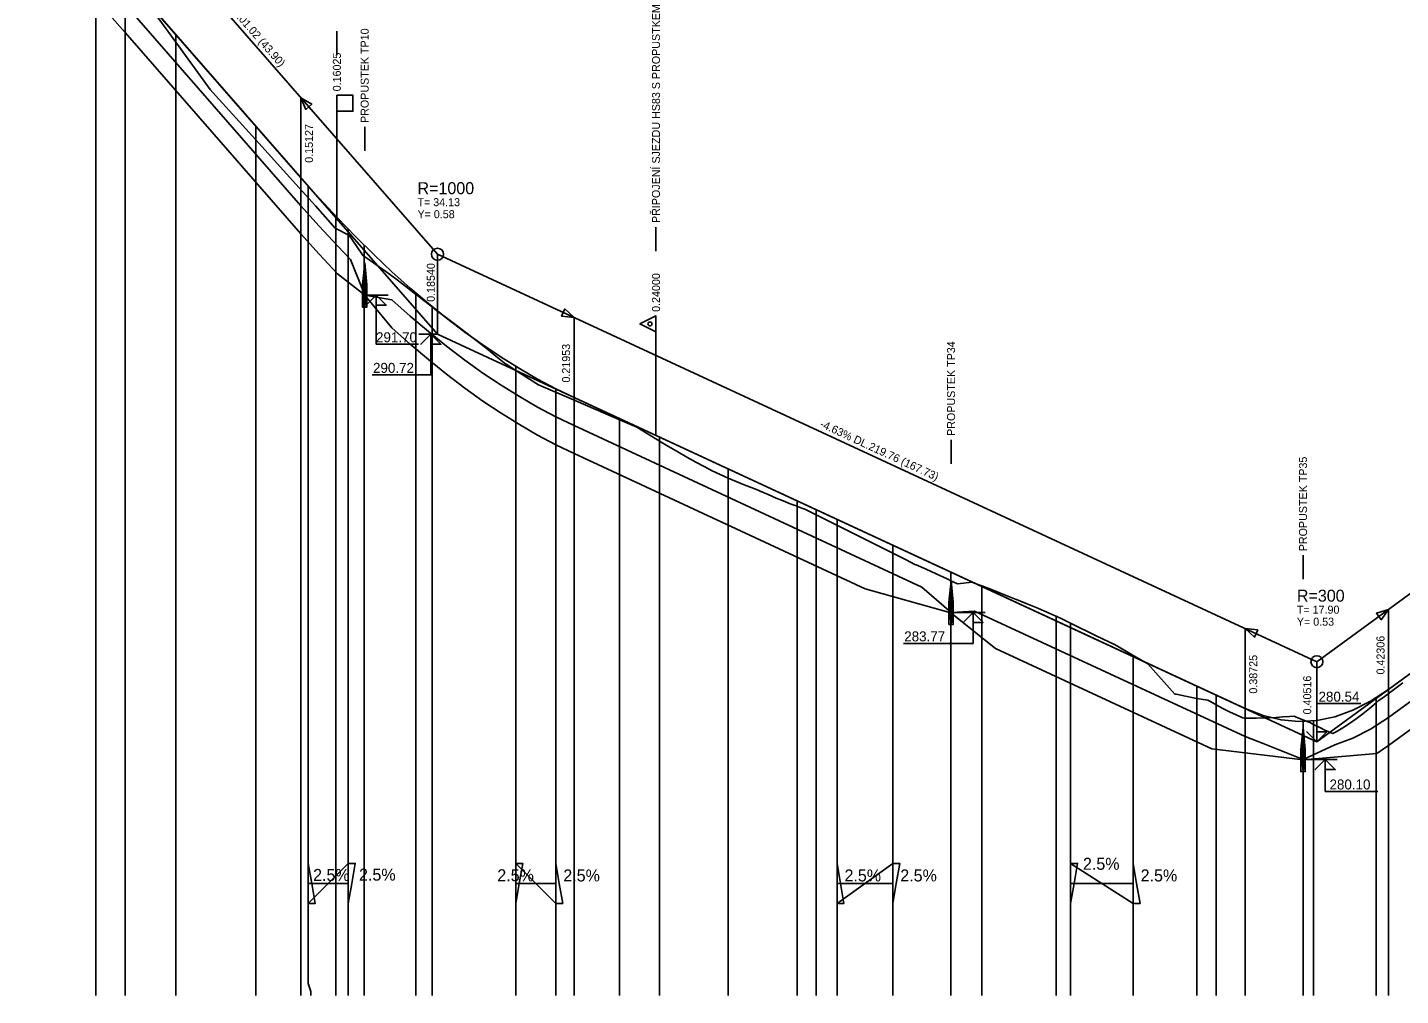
# Model space of a CAD drawing. Extents: x -24 to 1036, y -50 to 554.
# Drawn here: x 152.9 to 496.1, y 87 to 328.9 of the extents above; entities that cross this region are included whole.
import ezdxf

# ---------------------------------------------------------------- set-up
doc = ezdxf.new("R2010")
doc.units = 0
for name, color, linetype in [('KOTA', 7, 'Continuous'), ('KOTA_AUTOMAT', 7, 'Continuous'), ('KRIZENI', 7, 'Continuous'), ('KRIZENI_AUTOMAT', 7, 'Continuous'), ('NOVY_STAV', 7, 'Continuous'), ('NS_OBLOUK', 7, 'Continuous'), ('POPISY_NAD_TERENEM', 7, 'Continuous'), ('PRIKOPY', 7, 'Continuous'), ('REZY_PO', 7, 'Continuous'), ('SKLONOVE_POMERY', 7, 'Continuous'), ('SKLONOVE_POMERY_PROPOJENI', 7, 'Continuous'), ('SVK', 7, 'Continuous'), ('SVK_STAT', 7, 'Continuous'), ('ZNACKY', 7, 'Continuous')]:
    doc.layers.add(name, color=color, linetype=linetype)

msp = doc.modelspace()

# ---------------------------------------------------------------- linework, layer by layer
at = {"layer": 'KOTA'}
for points in [[(253.75, 252.21), (251.25, 249.71), (253.75, 252.21), (253.75, 242.06), (239.09, 242.06)], [(255.4, 252.21), (253.75, 252.21), (250.75, 252.21)], [(253.75, 252.21), (256.25, 249.71), (253.75, 249.71), (253.75, 252.21)], [(253.75, 252.21), (256.25, 249.71), (253.75, 249.71)], [(475.16, 150.4), (472.66, 152.9), (475.16, 150.4), (475.16, 159.92), (486.16, 159.92)], [(475.16, 150.4), (477.66, 152.9), (475.16, 152.9), (475.16, 150.4)], [(475.16, 150.4), (477.66, 152.9), (475.16, 152.9)], [(475.16, 150.4), (475.16, 150.4)], [(471.69, 145.96), (477.24, 145.96), (480.24, 145.96)], [(477.24, 145.96), (474.74, 143.46), (477.24, 145.96), (477.24, 138.01), (490.4, 138.01)], [(477.24, 145.96), (479.74, 143.46), (477.24, 143.46), (477.24, 145.96)], [(477.24, 145.96), (479.74, 143.46), (477.24, 143.46)]]:
    msp.add_lwpolyline(points, dxfattribs=at)
at = {"layer": 'KOTA_AUTOMAT'}
for points in [[(237.2, 262.02), (240.1, 262.02), (243.1, 262.02)], [(240.1, 262.02), (237.6, 259.52), (240.1, 262.02), (240.1, 249.71), (250.63, 249.71)], [(240.1, 262.02), (242.6, 259.52), (240.1, 259.52), (240.1, 262.02)], [(240.1, 262.02), (242.6, 259.52), (240.1, 259.52)], [(389.23, 182.7), (386.73, 180.2), (389.23, 182.7), (389.23, 174.98), (371.84, 174.98)], [(383.74, 182.7), (389.23, 182.7), (392.23, 182.7)], [(389.23, 182.7), (391.73, 180.2), (389.23, 180.2), (389.23, 182.7)], [(389.23, 182.7), (391.73, 180.2), (389.23, 180.2)]]:
    msp.add_lwpolyline(points, dxfattribs=at)
at = {"layer": 'KRIZENI'}
for points in [[(472.24, 148.46), (471.69, 153.96), (471.14, 148.46), (471.69, 142.96)], [(471.94, 148.46), (471.69, 150.96), (471.44, 148.46), (471.69, 145.96)]]:
    msp.add_lwpolyline(points, close=True, dxfattribs=at)
msp.add_lwpolyline([(471.14, 148.46), (471.14, 142.96), (472.24, 142.96), (472.24, 148.46)], dxfattribs=at)
at = {"layer": 'KRIZENI_AUTOMAT'}
for points in [[(237.75, 264.52), (237.2, 270.02), (236.65, 264.52), (237.2, 259.02)], [(237.45, 264.52), (237.2, 267.02), (236.95, 264.52), (237.2, 262.02)], [(384.29, 185.2), (383.74, 190.7), (383.19, 185.2), (383.74, 179.7)], [(383.99, 185.2), (383.74, 187.7), (383.49, 185.2), (383.74, 182.7)]]:
    msp.add_lwpolyline(points, close=True, dxfattribs=at)
for points in [[(236.65, 264.52), (236.65, 259.02), (237.75, 259.02), (237.75, 264.52)], [(383.19, 185.2), (383.19, 179.7), (384.29, 179.7), (384.29, 185.2)]]:
    msp.add_lwpolyline(points, dxfattribs=at)
at = {"layer": 'NOVY_STAV'}
for points in [[(70, 416.16), (154.38, 367.96), (255.4, 252.21), (475.16, 150.4), (545.37, 201.67), (768.49, 157.64), (859.4, 190.25)], [(154.38, 387.96), (255.4, 272.21)], [(177.37, 341.62), (221.27, 291.32), (225.82, 286.21), (230.37, 281.3), (234.92, 276.61), (239.47, 272.12), (244.02, 267.83), (248.57, 263.76), (253.12, 259.89), (257.67, 256.23), (262.22, 252.77), (266.77, 249.53), (271.32, 246.49), (275.88, 243.65), (280.43, 241.03), (284.98, 238.61), (289.53, 236.4), (457.25, 158.69), (461.73, 156.95), (466.21, 155.88), (470.68, 155.48), (475.16, 155.74), (479.63, 156.67), (484.11, 158.27), (488.58, 160.54), (493.06, 163.47), (522.18, 184.74)], [(255.4, 252.21), (255.4, 272.21)], [(255.4, 272.21), (475.16, 170.4)], [(475.16, 170.4), (545.37, 221.67)], [(475.16, 150.4), (475.16, 170.4)]]:
    msp.add_lwpolyline(points, dxfattribs=at)
for centre in [(255.4, 272.21), (475.16, 170.4)]:
    msp.add_circle(centre, 1.5, dxfattribs=at)
at = {"layer": 'NS_OBLOUK'}
for points in [[(221.27, 291.32), (221.27, 311.32)], [(221.27, 311.32), (223.99, 309.71), (222.49, 308.4), (221.27, 311.32)], [(289.53, 256.4), (287.23, 258.56), (286.39, 256.75), (289.53, 256.4)], [(289.53, 236.4), (289.53, 256.4)], [(493.06, 183.47), (490.05, 182.51), (491.23, 180.9), (493.06, 183.47)], [(493.06, 163.47), (493.06, 183.47)], [(457.25, 158.69), (457.25, 178.69)], [(457.25, 178.69), (460.4, 178.34), (459.56, 176.52), (457.25, 178.69)]]:
    msp.add_lwpolyline(points, dxfattribs=at)
for points in [[(221.27, 311.32), (223.99, 309.71), (222.49, 308.4)], [(289.53, 256.4), (287.23, 258.56), (286.39, 256.75)], [(493.06, 183.47), (490.05, 182.51), (491.23, 180.9)], [(457.25, 178.69), (460.4, 178.34), (459.56, 176.52)]]:
    msp.add_lwpolyline(points, close=True, dxfattribs=at)
at = {"layer": 'POPISY_NAD_TERENEM'}
for points in [[(230.25, 321.97), (230.25, 327.97)], [(237.2, 298), (237.2, 304)], [(310, 273), (310, 279)], [(383.74, 219.82), (383.74, 225.82)], [(471.69, 191), (471.69, 197)]]:
    msp.add_lwpolyline(points, dxfattribs=at)
at = {"layer": 'PRIKOPY'}
for points in [[(177.37, 334.62), (221.27, 284.32), (225.82, 279.21), (230.37, 274.3), (233.7, 270.9), (237.2, 262.02), (244.02, 260.83), (248.57, 256.76), (253.12, 252.89), (257.67, 249.23), (262.22, 245.77), (266.77, 242.53), (271.32, 239.49), (275.88, 236.65), (280.43, 234.03), (284.98, 231.61), (289.53, 229.4), (376.47, 189.03), (383.74, 182.7), (389.62, 183.04), (457.25, 151.69), (461.73, 149.95), (471.69, 145.96), (479.63, 149.67), (484.11, 151.27), (488.58, 153.54), (493.06, 156.47), (522.18, 177.74)], [(172.77, 332.76), (177.37, 327.62), (221.27, 277.32), (225.82, 272.21), (230.37, 267.3), (237.14, 262.04), (244.02, 253.83), (248.57, 249.76), (253.12, 245.89), (257.67, 242.23), (262.22, 238.77), (266.77, 235.53), (271.32, 232.49), (275.88, 229.65), (280.43, 227.03), (284.98, 224.61), (289.53, 222.4), (362.24, 188.64), (383.72, 182.6), (394.86, 173.74), (448.92, 148.64), (471.74, 145.9), (490.16, 147.47), (493.06, 149.47), (522.18, 170.74)]]:
    msp.add_lwpolyline(points, dxfattribs=at)
at = {"layer": 'REZY_PO'}
msp.add_lwpolyline([(184.41, 332.89), (190, 325.2), (198.62, 313.33), (200, 311.8), (210, 300.75), (220, 289.7), (224.91, 284.27), (229.84, 278.71), (230, 278.63), (233.1, 277.02), (233.43, 276.84), (235.11, 274.38), (236.85, 271.83), (237.12, 271.65), (238.56, 270.66), (240, 269.65), (242.5, 267.87), (245, 266.03), (247.5, 264.13), (249.91, 262.26), (250, 262.19), (252.02, 260.64), (254.04, 259.05), (255.77, 257.66), (256.03, 257.48), (258.01, 256.03), (260, 254.55), (262.5, 252.66), (265, 250.74), (267.5, 248.78), (270, 246.78), (272.49, 244.77), (272.54, 244.72), (274.98, 243.19), (280, 239.99), (280.66, 239.57), (290, 235.55), (300, 231.25), (305.2, 229.01), (310, 226.08), (310.82, 225.58), (310.85, 225.56), (310.88, 225.54), (313.16, 224.16), (315.44, 222.82), (317.72, 221.52), (320, 220.25), (322.02, 219.16), (324.03, 218.11), (324.05, 218.1), (326.05, 217.17), (328.07, 216.27), (329.03, 215.85), (330, 215.44), (332, 214.62), (334, 213.83), (335.53, 213.26), (336, 213.04), (338, 212.14), (340, 211.28), (341.75, 210.56), (343.5, 209.87), (345.25, 209.23), (345.28, 209.22), (345.31, 209.21), (347.16, 208.54), (350, 207.12), (360, 202.11), (369.18, 197.51), (369.2, 197.51), (369.21, 197.5), (369.6, 197.3), (369.7, 197.25), (370, 197.11), (372.5, 195.85), (374.68, 194.71), (375, 194.58), (377.5, 193.5), (380, 192.38), (381.85, 191.52), (382.78, 191.07), (383.69, 190.63), (385.31, 189.83), (386.85, 190.03), (388.95, 190.27), (390, 189.89), (390.7, 189.64), (391.4, 189.38), (394.26, 188.29), (397.13, 187.15), (400, 185.97), (400.07, 185.94), (402.5, 184.97), (405, 183.94), (407.5, 182.87), (409.91, 181.81), (410, 181.77), (411.79, 180.92), (413.58, 180.05), (413.6, 180.04), (413.61, 180.03), (420, 176.9), (424.73, 174.59), (430, 171.53), (432.9, 169.85), (439.67, 162.33), (440, 162.27), (445.06, 161.24), (445.1, 161.23), (445.13, 161.22), (446.75, 160.94), (447.87, 160.82), (448.38, 160.52), (450, 159.61), (451.67, 158.72), (453.33, 157.89), (455, 157.11), (456.67, 156.4), (457.03, 156.26), (458.33, 156.28), (459.44, 156.32), (460, 156.32), (461.67, 156.36), (463.33, 156.42), (465, 156.49), (466.67, 156.59), (468.33, 156.7), (469.51, 156.79), (470, 156.58), (471.44, 155.98), (472.88, 155.41), (473.41, 155.22), (474.33, 154.74), (475.74, 154.02), (477.16, 153.34), (478.58, 152.7), (479.17, 152.45), (480, 152.91), (481.67, 153.9), (483.33, 154.98), (485, 156.15), (486.67, 157.41), (488.33, 158.74), (490, 160.16), (490.5, 160.6), (491.67, 161.4), (493.33, 162.59), (495, 163.84), (496.67, 165.13)], dxfattribs=at)
at = {"layer": 'SKLONOVE_POMERY'}
for points in [[(223.1, 110), (223.1, 120), (223.1, 120), (223.97, 115), (224.83, 110), (223.1, 110)], [(233.1, 110), (233.1, 120), (234.83, 120), (233.97, 115), (233.1, 110), (233.1, 110)], [(274.98, 110), (274.98, 120), (276.71, 120), (275.84, 115), (274.98, 110), (274.98, 110)], [(284.98, 110), (284.98, 120), (284.98, 120), (285.84, 115), (286.71, 110), (284.98, 110)], [(355.25, 110), (355.25, 120), (355.25, 120), (356.11, 115), (356.98, 110), (355.25, 110)], [(369.18, 110), (369.18, 120), (370.91, 120), (370.05, 115), (369.18, 110), (369.18, 110)], [(413.61, 110), (413.61, 120), (415.34, 120), (414.47, 115), (413.61, 110), (413.61, 110)], [(429.26, 110), (429.26, 120), (429.26, 120), (430.12, 115), (430.99, 110), (429.26, 110)]]:
    msp.add_lwpolyline(points, dxfattribs=at)
at = {"layer": 'SKLONOVE_POMERY_PROPOJENI'}
for points in [[(223.1, 110), (233.1, 120)], [(274.98, 120), (284.98, 110)], [(355.25, 110), (369.18, 120)], [(413.61, 120), (429.26, 110)], [(223.1, 115), (233.1, 115)], [(274.98, 115), (284.98, 115)], [(355.25, 115), (369.18, 115)], [(413.61, 115), (429.26, 115)]]:
    msp.add_lwpolyline(points, dxfattribs=at)
at = {"layer": 'SVK'}
for points in [[(190, 87), (190, 327.15)], [(210, 87), (210, 304.23)], [(230, 87), (230, 281.7)], [(250, 87), (250, 262.54)], [(350, 87), (350, 208.38)], [(383.69, 87), (383.69, 192.77)], [(410, 87), (410, 181.77)], [(450, 87), (450, 162.05)], [(490, 87), (490, 161.47)]]:
    msp.add_lwpolyline(points, dxfattribs=at)
at = {"layer": 'SVK_STAT'}
for points in [[(170, 87), (170, 349.69)], [(177.37, 87), (177.37, 341.62)], [(221.27, 87), (221.27, 291.32)], [(223.77, 87), (223.77, 88), (223.1, 90), (223.1, 289.26)], [(233.1, 87), (233.1, 278.48)], [(237.11, 87), (237.11, 274.44)], [(254.04, 87), (254.04, 259.15)], [(274.98, 87), (274.98, 244.21)], [(284.98, 87), (284.98, 238.61)], [(289.53, 87), (289.53, 236.4)], [(300.88, 87), (300.88, 231.14)], [(310.88, 87), (310.88, 226.5)], [(328.07, 87), (328.07, 218.54)], [(345.25, 87), (345.25, 210.58)], [(355.25, 87), (355.25, 205.95)], [(369.21, 87), (369.21, 199.48)], [(391.4, 87), (391.4, 189.38)], [(413.58, 87), (413.58, 180.05)], [(429.26, 87), (429.26, 171.96)], [(445.13, 87), (445.13, 164.31)], [(493.06, 87), (493.06, 163.47)], [(457.25, 87), (457.25, 158.69)], [(471.69, 87), (471.69, 155.88)], [(474.33, 87), (474.33, 155.69)]]:
    msp.add_lwpolyline(points, dxfattribs=at)
at = {"layer": 'ZNACKY'}
for points in [[(230.25, 281.43), (230.25, 311.91), (234.25, 311.91), (234.25, 307.91), (230.25, 307.91)], [(310, 226.91), (310, 256.81), (306, 254.81), (310, 252.81)]]:
    msp.add_lwpolyline(points, dxfattribs=at)
msp.add_circle((308.5, 254.81), 0.5, dxfattribs=at)

# ---------------------------------------------------------------- texts
at = {"layer": 'KOTA'}
for s, p in [('290.72', (239.29, 242.56)), ('280.54', (475.57, 160.42)), ('280.10', (478.32, 138.48))]:
    msp.add_text(s, height=2.5, dxfattribs=at).set_placement(p)
at = {"layer": 'KOTA_AUTOMAT'}
for s, p in [('291.70', (240.04, 250.21)), ('283.77', (372.04, 175.48))]:
    msp.add_text(s, height=2.5, dxfattribs=at).set_placement(p)
at = {"layer": 'NOVY_STAV'}
for s, rotation, p in [('-11.46% DL.101.02 (43.90)', 311.111, (194.83, 343.13)), (' 0.18540', 90, (254.73, 259.57)), ('-4.63% DL.219.76 (167.73)', 335.143, (350.78, 229.12)), (' 0.40516', 90, (473.74, 156.5))]:
    msp.add_text(s, height=2, rotation=rotation, dxfattribs=at).set_placement(p)
at = {"layer": 'NS_OBLOUK'}
for s, p in [(' 0.15127', (224.27, 294.32)), (' 0.21953', (288.53, 239.4)), (' 0.42306', (492.06, 166.47)), (' 0.38725', (460.25, 161.69))]:
    msp.add_text(s, height=2, rotation=90, dxfattribs=at).set_placement(p)
for s, height, p in [('R=1000', 3, (250.4, 287.21)), ('T= 34.13', 2, (250.4, 284.21)), ('Y= 0.58', 2, (250.4, 281.21)), ('R=300', 3, (470.16, 185.4)), ('T= 17.90', 2, (470.16, 182.4)), ('Y= 0.53', 2, (470.16, 179.4))]:
    msp.add_text(s, height=height, dxfattribs=at).set_placement(p)
at = {"layer": 'POPISY_NAD_TERENEM'}
for s, p in [('PŘIPOJENÍ SJEZDU HS83 S PROPUSTKEM ', (311, 280)), ('PROPUSTEK TP10', (238.2, 305)), ('PROPUSTEK TP34', (384.74, 226.82)), ('PROPUSTEK TP35', (472.69, 198))]:
    msp.add_text(s, height=2, rotation=90, dxfattribs=at).set_placement(p)
at = {"layer": 'SKLONOVE_POMERY'}
for p in [(416.7, 118.41), (224.31, 115.62), (235.79, 115.71), (270.35, 115.54), (286.84, 115.5), (357.11, 115.5), (371.05, 115.5), (431.12, 115.5)]:
    msp.add_text('2.5%', height=3, dxfattribs=at).set_placement(p)
at = {"layer": 'ZNACKY'}
for s, p in [('0.16025', (231.25, 312.91)), ('0.24000', (311, 257.81))]:
    msp.add_text(s, height=2, rotation=90, dxfattribs=at).set_placement(p)

doc.saveas('drawing.dxf')
